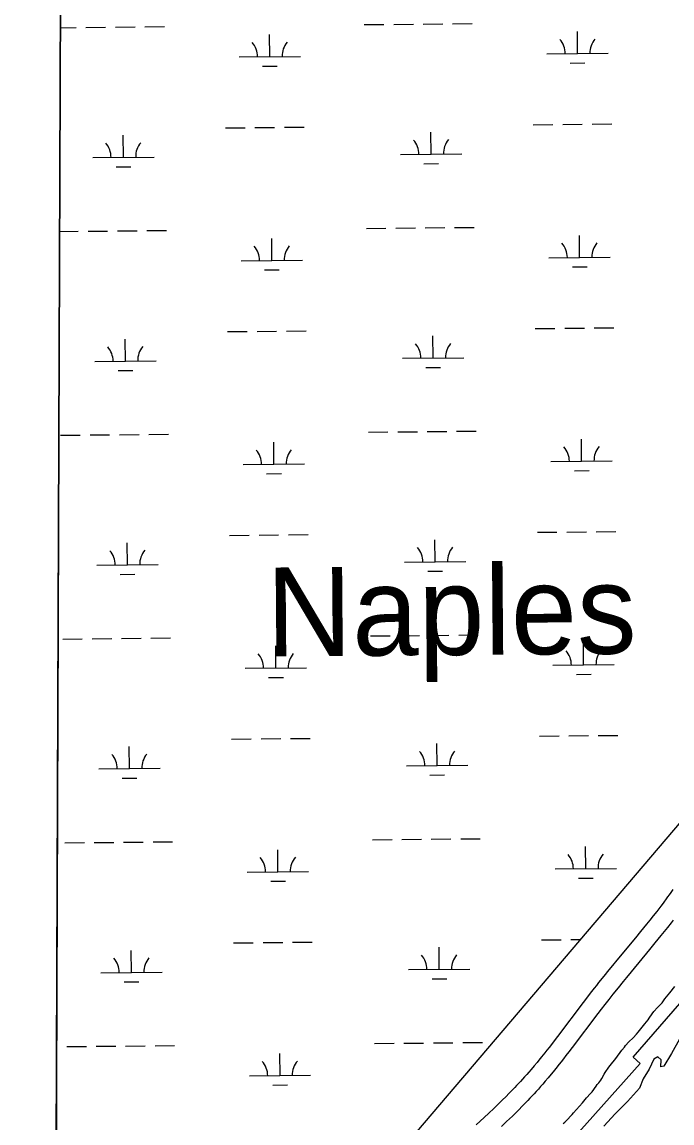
# Model space of a CAD drawing. Extents: x 3146026 to 3183936, y 897894 to 923344.
# Drawn here: x 3150246 to 3151306, y 918770 to 920567 of the extents above; entities that cross this region are included whole.
import ezdxf

# ---------------------------------------------------------------- set-up
doc = ezdxf.new("R2010")
doc.units = 0
for name, color, linetype in [('V-GRID-FRAM', 7, 'Continuous'), ('V-RIVR-EDGE', 7, 'Continuous'), ('V-ROAD-CNTR', 7, 'Continuous'), ('V-RRAP-RVMT', 7, 'Continuous'), ('V-SITE-VEGE', 7, 'Continuous'), ('V-TOPO-GNAM-IDEN', 7, 'Continuous'), ('V-WETL-SWMP', 7, 'Continuous')]:
    doc.layers.add(name, color=color, linetype=linetype)

msp = doc.modelspace()

# ---------------------------------------------------------------- linework, layer by layer
at = {"layer": 'V-GRID-FRAM'}
msp.add_lwpolyline([(3150311.9, 921563.1), (3181637, 921462.9), (3181586.7, 903274.3), (3150245.8, 903374.5), (3150311.9, 921563.1)], dxfattribs=at)
at = {"layer": 'V-RIVR-EDGE'}
msp.add_lwpolyline([(3151318.1, 918907.1), (3151305.2, 918883.7), (3151292.4, 918862.8), (3151287.7, 918861.5), (3151288, 918873.4), (3151282.7, 918877.8), (3151276.1, 918874.1), (3151268.3, 918857.8), (3151258.6, 918841.9), (3151252.6, 918826.9), (3151233.1, 918805.1), (3151213.1, 918785.2), (3151194.6, 918764.9)], dxfattribs=at)
at = {"layer": 'V-ROAD-CNTR'}
for points in [[(3151307, 919151), (3151303.9, 919146.4), (3151301.1, 919142.5), (3151298.6, 919139), (3151296.4, 919136), (3151292.6, 919130.7), (3151289.7, 919126.8), (3151287.5, 919123.9), (3151284.2, 919119.6), (3151280.8, 919115.3), (3151275, 919108), (3151269.5, 919101.2), (3151264.4, 919094.9), (3151254.6, 919082.9), (3151246.1, 919072.5), (3151216, 919036), (3151208.5, 919026.9), (3151202.9, 919020), (3151194.4, 919009.6), (3151186.1, 918999.2), (3151182.5, 918994.7), (3151179.1, 918990.4), (3151172.6, 918982), (3151166.5, 918974.1), (3151160.8, 918966.7), (3151119, 918911.2), (3151113.8, 918904.4)], [(3151307.8, 919101.2), (3151304.3, 919096.7), (3151298.4, 919089.3), (3151292.9, 919082.4), (3151287.6, 919075.9), (3151277.9, 919063.9), (3151269.3, 919053.5), (3151239.2, 919017), (3151231.7, 919007.8), (3151226.1, 919001), (3151217.8, 918990.7), (3151209.5, 918980.4), (3151206, 918976.1), (3151202.7, 918971.9), (3151196.3, 918963.6), (3151190.3, 918955.9), (3151184.7, 918948.6), (3151142.9, 918893.1), (3151137.6, 918886.2)], [(3151113.8, 918904.4), (3151109.2, 918898.4), (3151105.2, 918893.2), (3151101.6, 918888.7), (3151098.5, 918884.7), (3151093, 918877.9), (3151088.8, 918872.7), (3151085.7, 918868.9), (3151081, 918863.2), (3151076.2, 918857.6), (3151072.5, 918853.3), (3151069, 918849.2), (3151065.5, 918845.3), (3151062.1, 918841.5), (3151058.7, 918837.9), (3151055.5, 918834.4), (3151052.3, 918831), (3151049.2, 918827.8), (3151046.2, 918824.6), (3151040.3, 918818.6), (3151034.7, 918812.9), (3151029.4, 918807.7), (3151024.4, 918802.8), (3151019.7, 918798.2), (3151015.3, 918793.9), (3151006.9, 918785.9), (3150999.5, 918778.9), (3150986.5, 918766.8)], [(3151137.6, 918886.1), (3151132.9, 918880.1), (3151128.8, 918874.8), (3151125.2, 918870.1), (3151122, 918866.1), (3151116.3, 918859), (3151112.1, 918853.8), (3151108.8, 918849.8), (3151104, 918843.9), (3151099, 918838.1), (3151095.2, 918833.7), (3151091.4, 918829.4), (3151087.8, 918825.3), (3151084.2, 918821.3), (3151080.8, 918817.6), (3151077.4, 918813.9), (3151074.1, 918810.4), (3151070.9, 918807), (3151067.7, 918803.8), (3151061.7, 918797.5), (3151055.9, 918791.7), (3151050.5, 918786.3), (3151045.4, 918781.3), (3151040.6, 918776.6), (3151036, 918772.3), (3151027.5, 918764.2)]]:
    msp.add_lwpolyline(points, dxfattribs=at)
at = {"layer": 'V-RRAP-RVMT'}
for p, q in [((3151242.7, 918877.6), (3151329.4, 918977.7)), ((3151079.3, 918671.8), (3151254.1, 918867.3)), ((3151254.1, 918867.3), (3151242.7, 918877.6))]:
    msp.add_line(p, q, dxfattribs=at)
at = {"layer": 'V-SITE-VEGE'}
for p, q in [((3150311.9, 921563.1), (3150298.1, 917768.5)), ((3151302.3, 918982.7), (3151310.5, 918992.7)), ((3151294.3, 918972.5), (3151299.8, 918979.3)), ((3151299.8, 918979.3), (3151302.3, 918982.7)), ((3151276.3, 918951.8), (3151282.1, 918958.6)), ((3151282.1, 918958.6), (3151289.6, 918966.4)), ((3151289.6, 918966.4), (3151294.3, 918972.5)), ((3151266.9, 918938.4), (3151268.5, 918941.1)), ((3151268.5, 918941.1), (3151273.6, 918948.4)), ((3151273.6, 918948.4), (3151276.3, 918951.8)), ((3151250.4, 918918.4), (3151259.3, 918929.2)), ((3151259.3, 918929.2), (3151261.3, 918931.8)), ((3151261.3, 918931.8), (3151266.9, 918938.4)), ((3151235.3, 918902.3), (3151242.4, 918909.2)), ((3151242.4, 918909.2), (3151247.9, 918915.3)), ((3151247.9, 918915.3), (3151250.4, 918918.4)), ((3151214, 918875.3), (3151224.2, 918889.2)), ((3151224.2, 918889.2), (3151228.3, 918894.1)), ((3151228.3, 918894.1), (3151230, 918896.7)), ((3151230, 918896.7), (3151235.3, 918902.3)), ((3151205, 918863.9), (3151214, 918875.3)), ((3151191.4, 918842.7), (3151195.1, 918849.7)), ((3151195.1, 918849.7), (3151196.8, 918852.7)), ((3151196.8, 918852.7), (3151202.6, 918861.2)), ((3151202.6, 918861.2), (3151205, 918863.9)), ((3151182.2, 918830), (3151183.9, 918832.7)), ((3151183.9, 918832.7), (3151186.4, 918835.4)), ((3151186.4, 918835.4), (3151189.5, 918839.8)), ((3151189.5, 918839.8), (3151191.4, 918842.7)), ((3151166.2, 918811), (3151173, 918818.1)), ((3151173, 918818.1), (3151175.5, 918821)), ((3151175.5, 918821), (3151182.2, 918830)), ((3151144.9, 918786.4), (3151155.1, 918797.4)), ((3151155.1, 918797.4), (3151159.7, 918802.7)), ((3151159.7, 918802.7), (3151166.2, 918811)), ((3151133, 918773.7), (3151143.2, 918783.7)), ((3151143.2, 918783.7), (3151144.9, 918786.4)), ((3151128.4, 918769.1), (3151130.8, 918771.3)), ((3151130.8, 918771.3), (3151133, 918773.7))]:
    msp.add_line(p, q, dxfattribs=at)
at = {"layer": 'V-WETL-SWMP'}
for p, q in [((3150308.3, 920558.1), (3150334.1, 920558.4)), ((3150350.1, 920558.5), (3150382.1, 920558.9)), ((3150398.1, 920559), (3150430.1, 920559.3)), ((3150446.1, 920559.5), (3150478.1, 920559.8)), ((3150804, 920563.1), (3150836, 920563.4)), ((3150852, 920563.5), (3150884, 920563.9)), ((3150900, 920564), (3150932, 920564.3)), ((3150948, 920564.5), (3150980, 920564.8)), ((3150649.9, 920510.8), (3150649.6, 920546.8)), ((3151151.8, 920515.8), (3151151.4, 920551.8)), ((3150599.9, 920510.3), (3150699.9, 920511.3)), ((3151101.8, 920515.3), (3151201.8, 920516.3)), ((3150638.1, 920495.2), (3150662.1, 920495.5)), ((3151139.9, 920500.2), (3151163.9, 920500.5)), ((3150577.7, 920394.6), (3150609.7, 920394.9)), ((3150625.7, 920395.1), (3150657.7, 920395.4)), ((3150673.7, 920395.6), (3150705.7, 920395.9)), ((3151079.5, 920399.6), (3151111.5, 920399.9)), ((3151127.5, 920400.1), (3151159.5, 920400.4)), ((3151175.5, 920400.6), (3151207.5, 920400.9)), ((3150411.1, 920346.5), (3150410.7, 920382.5)), ((3150912.9, 920351.5), (3150912.6, 920387.5)), ((3150361.1, 920346), (3150461.1, 920347)), ((3150863, 920351), (3150962.9, 920352)), ((3150399.2, 920331), (3150423.2, 920331.2)), ((3150901.1, 920336), (3150925.1, 920336.2)), ((3150307.1, 920225.4), (3150337.4, 920225.7)), ((3150353.4, 920225.9), (3150385.4, 920226.2)), ((3150401.4, 920226.4), (3150433.4, 920226.7)), ((3150449.4, 920226.8), (3150481.4, 920227.2)), ((3150807.3, 920230.4), (3150839.3, 920230.7)), ((3150855.3, 920230.9), (3150887.3, 920231.2)), ((3150903.3, 920231.4), (3150935.3, 920231.7)), ((3150951.3, 920231.8), (3150983.3, 920232.2)), ((3151155.1, 920183.1), (3151154.8, 920219.1)), ((3150653.2, 920178.1), (3150652.9, 920214.1)), ((3151105.1, 920182.6), (3151205.1, 920183.6)), ((3150603.2, 920177.6), (3150703.2, 920178.6)), ((3150641.4, 920162.6), (3150665.4, 920162.8)), ((3151143.3, 920167.6), (3151167.3, 920167.8)), ((3150581, 920062), (3150613, 920062.3)), ((3150629, 920062.4), (3150661, 920062.8)), ((3150677, 920062.9), (3150709, 920063.2)), ((3150916.3, 920018.9), (3150915.9, 920054.9)), ((3151082.9, 920067), (3151114.9, 920067.3)), ((3151130.9, 920067.5), (3151162.9, 920067.8)), ((3151178.9, 920067.9), (3151210.8, 920068.2)), ((3150414.4, 920013.9), (3150414, 920049.9)), ((3150866.3, 920018.4), (3150966.3, 920019.4)), ((3150364.4, 920013.4), (3150464.4, 920014.4)), ((3150904.4, 920003.3), (3150928.4, 920003.6)), ((3150402.5, 919998.3), (3150426.5, 919998.6)), ((3150308.7, 919892.7), (3150340.7, 919893.1)), ((3150356.7, 919893.2), (3150388.7, 919893.5)), ((3150404.7, 919893.7), (3150436.7, 919894)), ((3150452.7, 919894.2), (3150484.7, 919894.5)), ((3150810.6, 919897.7), (3150842.6, 919898.1)), ((3150858.6, 919898.2), (3150890.6, 919898.5)), ((3150906.6, 919898.7), (3150938.6, 919899)), ((3150954.6, 919899.2), (3150986.6, 919899.5)), ((3150656.5, 919845.5), (3150656.2, 919881.5)), ((3151158.4, 919850.5), (3151158.1, 919886.5)), ((3150606.5, 919845), (3150706.5, 919846)), ((3151108.4, 919850), (3151208.4, 919851)), ((3150644.7, 919829.9), (3150668.7, 919830.2)), ((3151146.6, 919834.9), (3151170.6, 919835.2)), ((3150584.3, 919729.3), (3150616.3, 919729.6)), ((3150632.3, 919729.8), (3150664.3, 919730.1)), ((3150680.3, 919730.3), (3150712.3, 919730.6)), ((3151086.2, 919734.3), (3151118.2, 919734.6)), ((3151134.2, 919734.8), (3151166.2, 919735.1)), ((3151182.2, 919735.3), (3151214.2, 919735.6)), ((3150417.7, 919681.2), (3150417.3, 919717.2)), ((3150919.6, 919686.2), (3150919.2, 919722.2)), ((3150367.7, 919680.7), (3150467.7, 919681.7)), ((3150869.6, 919685.7), (3150969.6, 919686.7)), ((3150405.9, 919665.7), (3150429.8, 919665.9)), ((3150907.7, 919670.7), (3150931.7, 919670.9)), ((3150312.1, 919560.1), (3150344.1, 919560.4)), ((3150360.1, 919560.6), (3150392, 919560.9)), ((3150408, 919561), (3150440, 919561.4)), ((3150456, 919561.5), (3150488, 919561.8)), ((3150813.9, 919565.1), (3150845.9, 919565.4)), ((3150861.9, 919565.6), (3150893.9, 919565.9)), ((3150909.9, 919566), (3150941.9, 919566.4)), ((3150957.9, 919566.5), (3150989.9, 919566.8)), ((3151161.7, 919517.8), (3151161.4, 919553.8)), ((3150659.9, 919512.8), (3150659.5, 919548.8)), ((3151111.7, 919517.3), (3151211.7, 919518.3)), ((3150609.9, 919512.3), (3150709.9, 919513.3)), ((3150648, 919497.3), (3150672, 919497.5)), ((3151149.9, 919502.3), (3151173.9, 919502.5)), ((3150587.6, 919396.7), (3150619.6, 919397)), ((3150635.6, 919397.1), (3150667.6, 919397.5)), ((3150683.6, 919397.6), (3150715.6, 919397.9)), ((3150922.9, 919353.6), (3150922.5, 919389.6)), ((3151089.5, 919401.7), (3151121.5, 919402)), ((3151137.5, 919402.1), (3151169.5, 919402.5)), ((3151185.5, 919402.6), (3151217.5, 919402.9)), ((3150421, 919348.6), (3150420.7, 919384.6)), ((3150872.9, 919353.1), (3150972.9, 919354.1)), ((3150371, 919348.1), (3150471, 919349.1)), ((3150911, 919338), (3150935, 919338.3)), ((3150409.2, 919333), (3150433.2, 919333.2)), ((3150315.4, 919227.4), (3150347.4, 919227.7)), ((3150363.4, 919227.9), (3150395.4, 919228.2)), ((3150411.4, 919228.4), (3150443.4, 919228.7)), ((3150459.4, 919228.9), (3150491.4, 919229.2)), ((3150817.3, 919232.4), (3150849.3, 919232.8)), ((3150865.2, 919232.9), (3150897.2, 919233.2)), ((3150913.2, 919233.4), (3150945.2, 919233.7)), ((3150961.2, 919233.9), (3150993.2, 919234.2)), ((3150663.2, 919180.2), (3150662.8, 919216.2)), ((3151165.1, 919185.2), (3151164.7, 919221.2)), ((3150613.2, 919179.7), (3150713.2, 919180.7)), ((3151115.1, 919184.7), (3151215.1, 919185.7)), ((3150651.3, 919164.6), (3150675.3, 919164.8)), ((3151153.2, 919169.6), (3151177.2, 919169.8)), ((3150638.9, 919064.5), (3150670.9, 919064.8)), ((3150686.9, 919065), (3150718.9, 919065.3)), ((3151092.8, 919069), (3151124.8, 919069.3)), ((3151140.8, 919069.5), (3151156.9, 919069.6)), ((3150424.3, 919015.9), (3150424, 919051.9)), ((3150590.9, 919064), (3150622.9, 919064.3)), ((3150926.2, 919020.9), (3150925.9, 919056.9)), ((3150374.3, 919015.4), (3150474.3, 919016.4)), ((3150876.2, 919020.4), (3150976.2, 919021.4)), ((3150412.5, 919000.4), (3150436.5, 919000.6)), ((3150914.4, 919005.4), (3150938.4, 919005.6)), ((3150318.7, 918894.8), (3150350.7, 918895.1)), ((3150366.7, 918895.3), (3150398.7, 918895.6)), ((3150414.7, 918895.7), (3150446.7, 918896)), ((3150462.7, 918896.2), (3150494.7, 918896.5)), ((3150820.6, 918899.8), (3150852.6, 918900.1)), ((3150868.6, 918900.3), (3150900.6, 918900.6)), ((3150916.6, 918900.7), (3150948.6, 918901)), ((3150964.6, 918901.2), (3150996.6, 918901.5)), ((3150666.5, 918847.5), (3150666.1, 918883.5)), ((3150616.5, 918847), (3150716.5, 918848)), ((3150654.6, 918831.9), (3150678.6, 918832.2))]:
    msp.add_line(p, q, dxfattribs=at)
msp.add_lwpolyline([(3154156.3, 921550.8), (3150311.9, 921563.1), (3150299.2, 918069.2), (3150852.3, 918711.7), (3151740.5, 919755.3), (3152243.5, 920278.8), (3152339.1, 920369.4), (3152421.5, 920426.9), (3152514.9, 920450.7), (3152616.2, 920465.1), (3152932.2, 920578.6), (3153209.3, 920814.1), (3153778.6, 921266.6), (3154156.3, 921550.8)], dxfattribs=at)
for centre, start, end in [((3151096.5, 920515.7), 359.7992, 41.3429), ((3151207, 920516.8), 139.7992, 181.3429), ((3150594.7, 920510.7), 359.7992, 41.3429), ((3150705.1, 920511.8), 139.7992, 181.3429), ((3150355.8, 920346.5), 359.7992, 41.3429), ((3150466.3, 920347.6), 139.7992, 181.3429), ((3150857.7, 920351.5), 359.7992, 41.3429), ((3150968.2, 920352.6), 139.7992, 181.3429), ((3150598, 920178.1), 359.7992, 41.3429), ((3150708.5, 920179.2), 139.7992, 181.3429), ((3151099.9, 920183.1), 359.7992, 41.3429), ((3151210.3, 920184.2), 139.7992, 181.3429), ((3150359.1, 920013.8), 359.7992, 41.3429), ((3150469.6, 920014.9), 139.7992, 181.3429), ((3150861, 920018.8), 359.7992, 41.3429), ((3150971.5, 920019.9), 139.7992, 181.3429), ((3151103.2, 919850.4), 359.7992, 41.3429), ((3151213.7, 919851.5), 139.7992, 181.3429), ((3150601.3, 919845.4), 359.7992, 41.3429), ((3150711.8, 919846.5), 139.7992, 181.3429), ((3150362.5, 919681.1), 359.7992, 41.3429), ((3150472.9, 919682.2), 139.7992, 181.3429), ((3150864.3, 919686.1), 359.7992, 41.3429), ((3150974.8, 919687.2), 139.7992, 181.3429), ((3150604.6, 919512.7), 359.7992, 41.3429), ((3150715.1, 919513.8), 139.7992, 181.3429), ((3151106.5, 919517.7), 359.7992, 41.3429), ((3151217, 919518.8), 139.7992, 181.3429), ((3150365.8, 919348.5), 359.7992, 41.3429), ((3150476.2, 919349.6), 139.7992, 181.3429), ((3150867.6, 919353.5), 359.7992, 41.3429), ((3150978.1, 919354.6), 139.7992, 181.3429), ((3151220.3, 919186.2), 139.7992, 181.3429), ((3150607.9, 919180.1), 359.7992, 41.3429), ((3150718.4, 919181.2), 139.7992, 181.3429), ((3151109.8, 919185.1), 359.7992, 41.3429), ((3150369.1, 919015.8), 359.7992, 41.3429), ((3150479.6, 919016.9), 139.7992, 181.3429), ((3150871, 919020.8), 359.7992, 41.3429), ((3150981.4, 919021.9), 139.7992, 181.3429), ((3150611.2, 918847.4), 359.7992, 41.3429), ((3150721.7, 918848.5), 139.7992, 181.3429)]:
    msp.add_arc(centre, 35.2, start, end, dxfattribs=at)

# ---------------------------------------------------------------- texts
at = {"layer": 'V-TOPO-GNAM-IDEN'}
msp.add_text('Naples', height=145, rotation=0.4542, dxfattribs=at).set_placement((3150644.7, 919531.7))

doc.saveas('drawing.dxf')
